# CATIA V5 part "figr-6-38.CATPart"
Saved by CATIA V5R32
Part number: Part1
Bounding box of the stored display mesh (mm): x -36 to 36, y -66.608 to 66.608, z -13.545 to 13.545
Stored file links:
  D:\PROJECTS\Project 2022\CATIA V5 6R 2022\Resources\Part Files\c06_catia_v5_6r2022_prt\figr-6-38.CATPart
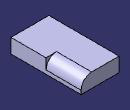
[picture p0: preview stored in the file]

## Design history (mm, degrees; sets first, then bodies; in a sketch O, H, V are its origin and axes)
Body1 (main body)
  Sketch1 on yz-plane, origin (0, 0, 0), H (0, 1, 0), V (0, 0, 1)
    line L1 (-66.6077, 13.5449) -> (66.6077, 13.5449)
    line L2 (66.6077, 13.5449) -> (66.6077, -13.5449)
    line L3 (66.6077, -13.5449) -> (-66.6077, -13.5449)
    line L4 (-66.6077, -13.5449) -> (-66.6077, 13.5449)
    axis line L5 (66.6077, -13.5449) -> (-66.6077, 13.5449)
    horizontal: L1 H, L3 H
    vertical: L2 V, L4 V
    midpoint: O L5
  Pad1: profile Sketch1, direction (1, 0, 0), length 36, mirrored extent
  Fillet1: radius 20, on edge [face of Pad1 | face of Pad1]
